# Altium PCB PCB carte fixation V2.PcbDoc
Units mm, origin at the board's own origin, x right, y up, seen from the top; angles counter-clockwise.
Board outline 50 x 70 mm, 2 copper layers (Top Layer, Bottom Layer); 0 components, 2 nets, 44 pads, 0 vias.
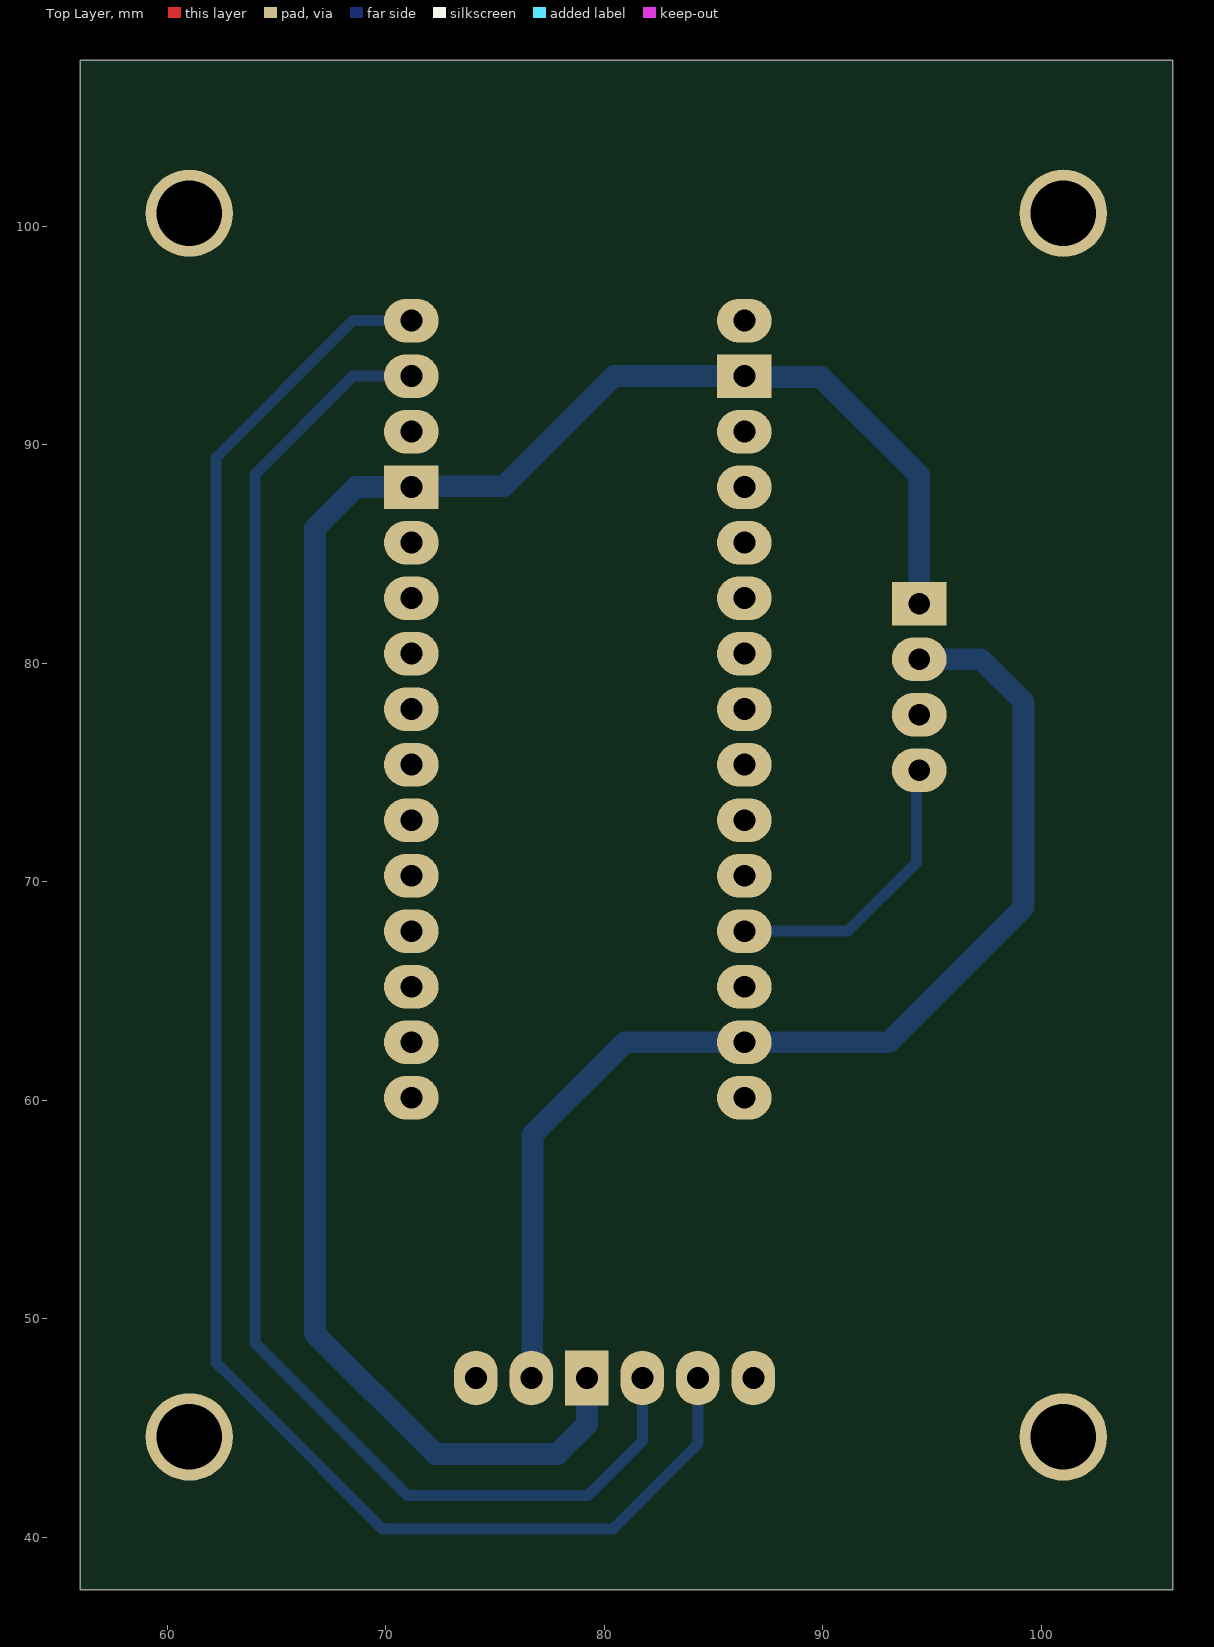
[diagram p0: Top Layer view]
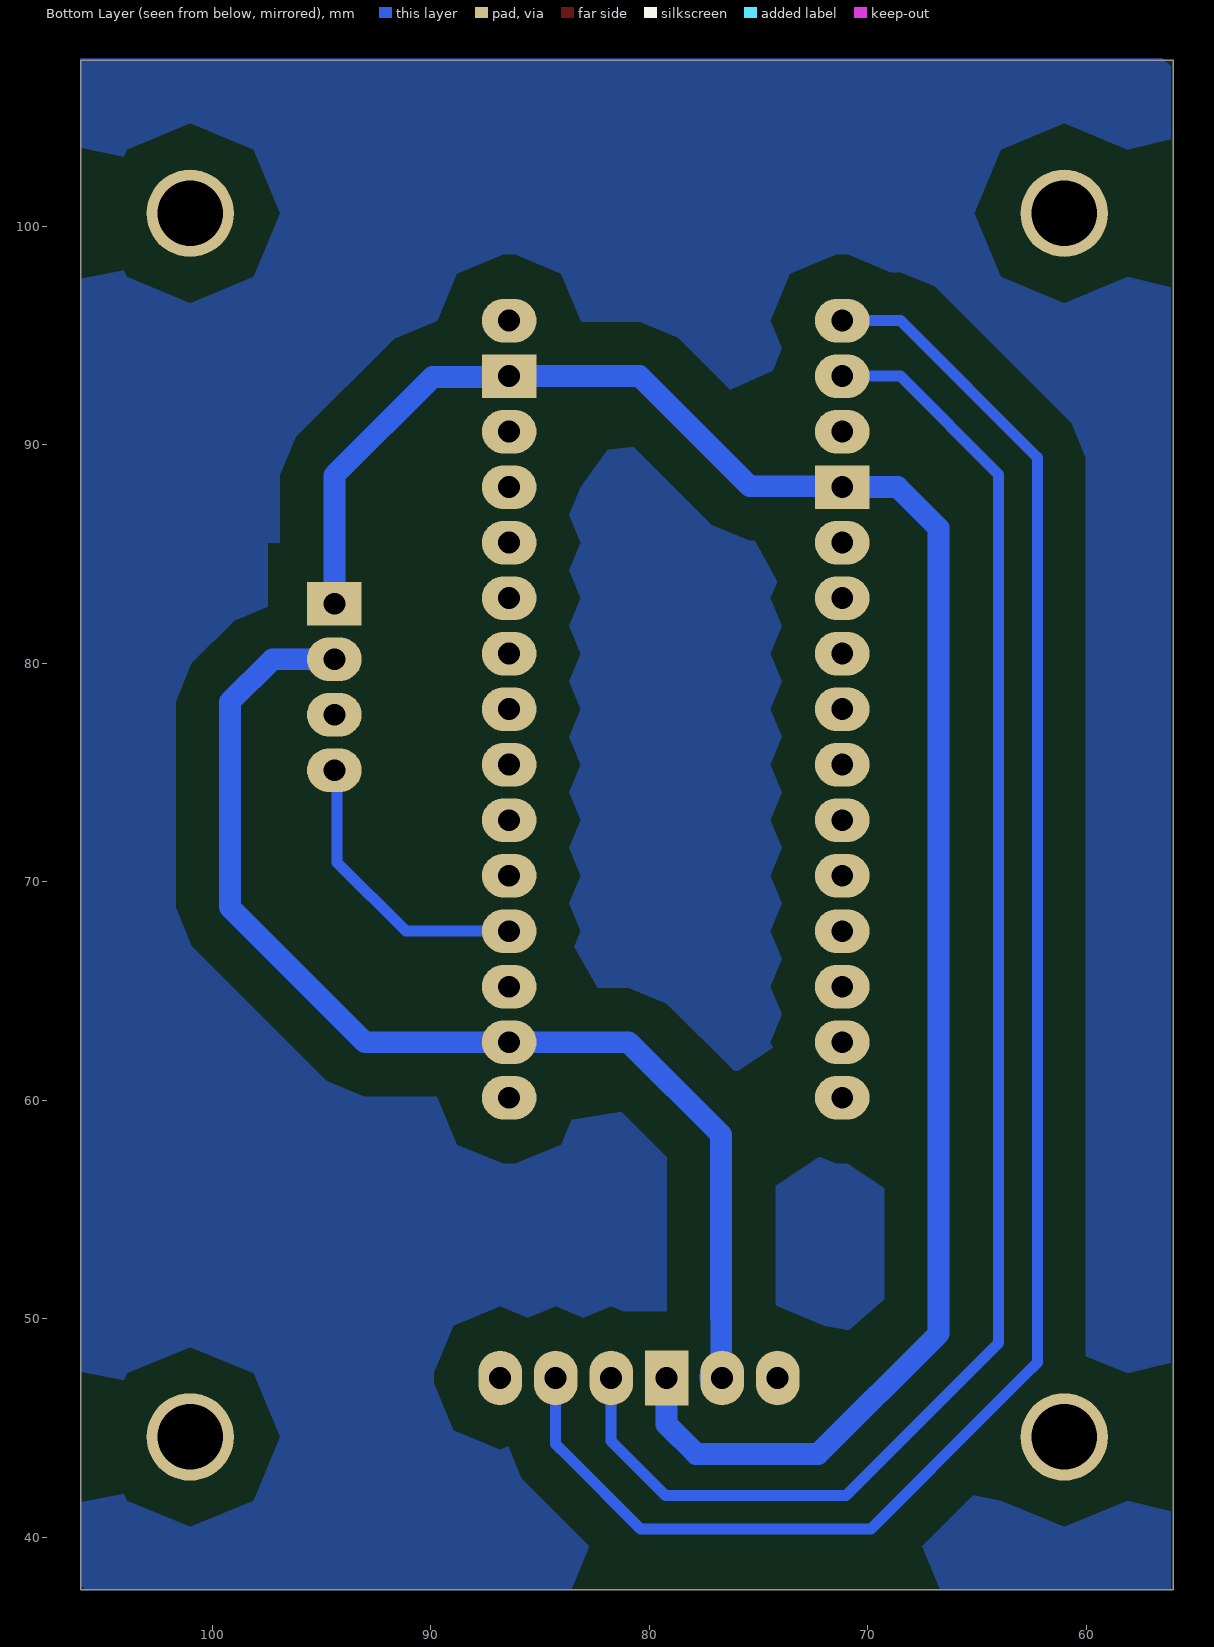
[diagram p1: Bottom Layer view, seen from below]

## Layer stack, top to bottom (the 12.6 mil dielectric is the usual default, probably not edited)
Top Solder: solder mask 0.0102, Solder Resist, Dk 3.5
Top Layer: signal copper 0.0356
Dielectric 1: dielectric 0.32, FR-4, Dk 4.8
Bottom Layer: signal copper 0.0356
Bottom Solder: solder mask 0.0102, Solder Resist, Dk 3.5

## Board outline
56.007,37.592 56.007,107.592 106.007,107.592 106.007,37.592

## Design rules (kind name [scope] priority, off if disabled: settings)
Clearance Keepout [ISPAD vs iskeepout or IsPad] p1: gap=0.05
Clearance Clearance_Plan [InPolygon] p2: gap=1.8
Clearance [All] p3: gap=0.5
PolygonConnect [All] p1: connectstyle=Relief reliefconductorwidth=0.254 reliefentries=4 polygonreliefangle="90 Angle" airgapwidth=0.254
RoutingVias [All] p1: holewidth=0.8 width=1.7 viastyle="Through Hole" minholewidth=0.8 minwidth=1.7 maxholewidth=0.8 maxwidth=1.7
SolderMaskExpansion [All] p1: expansion=0.102
Width LargeurePistesPuissance [InNet('ALIM') OR InNet('MASSE')] p1: maxlimit=2 minlimit=1 preferedwidth=2 minimp=50.000000 maximp=50.000000 favimp=50.000000
Width LargeurPistes [All] p2: maxlimit=1 minlimit=0.5 preferedwidth=0.8 minimp=50.000000 maximp=50.000000 favimp=50.000000
30 further rules are at their usual default settings.

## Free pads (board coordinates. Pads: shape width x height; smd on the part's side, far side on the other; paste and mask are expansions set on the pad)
  round 4 hole 3: 12(61.007,44.592) 12(61.007,100.592) 12(101.007,44.592) 12(101.007,100.592)
  oval 2.5x2 hole 1: 13(71.168,60.119) 13(71.168,62.659) 13(71.168,65.199) 13(71.168,67.739) 13(71.168,70.279) 13(71.168,72.819) 13(71.168,75.359) 13(71.168,77.899) 13(71.168,80.439) 13(71.168,82.979) 13(71.168,85.519) 13(71.168,90.599) 13(71.168,93.139) 13(71.168,95.679) 13(86.408,60.119) 13(86.408,62.659) 13(86.408,65.199) 13(86.408,67.739) 13(86.408,70.279) 13(86.408,72.819) 13(86.408,75.359) 13(86.408,77.899) 13(86.408,80.439) 13(86.408,82.979) 13(86.408,85.519) 13(86.408,88.059) 13(86.408,90.599) 13(86.408,95.679) 13(94.409,75.105) 13(94.409,77.645) 13(94.409,80.185)
  rect 2.5x2 hole 1: 13(71.168,88.059) 13(86.408,93.139) 13(94.409,82.725)
  oval 2x2.5 hole 1: 13(74.12,47.292) 13(76.66,47.292) 13(81.74,47.292) 13(84.28,47.292) 13(86.82,47.292)
  rect 2x2.5 hole 1: 13(79.2,47.292)

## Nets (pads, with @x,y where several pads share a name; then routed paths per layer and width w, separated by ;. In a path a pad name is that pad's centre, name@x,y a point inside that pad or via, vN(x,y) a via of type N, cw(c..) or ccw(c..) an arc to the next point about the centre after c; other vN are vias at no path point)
ALIM: pad.13@76.66,47.292 pad.13@86.408,62.659 pad.13@94.409,80.185 | length 52.9
  Bottom Layer w1: pad.13@76.7,47.332 76.7,50.082 76.708,50.09 76.708,58.42 80.947,62.659 86.408,62.659 93.012,62.659 99.187,68.834 99.187,78.232 97.234,80.185 pad.13@94.409,80.185
  Bottom Layer w2: pad.13@76.66,47.292 pad.13@76.7,47.332
MASSE: pad.13@71.168,88.059 pad.13@79.2,47.292 pad.13@86.408,93.139 pad.13@94.409,82.725 | length 91.2
  Bottom Layer w1: pad.13@71.168,88.059 68.628,88.059 66.754,86.185 66.754,49.324 72.263,43.815 77.851,43.815 79.2,45.164 pad.13@79.2,47.292 ; pad.13@71.208,88.099 75.399,88.099 80.439,93.139 pad.13@86.408,93.139 ; 87.694,93.099 89.908,93.099 94.409,88.598 pad.13@94.409,82.725
copper on no net: | length 170.2
  Top Layer w0.254: 81.806,46.373 81.806,47.244 ; 84.606,47.244 84.606,47.947
  Bottom Layer w0.5: 71.168,93.139 68.501,93.139 64.008,88.646 64.008,48.895 70.993,41.91 79.248,41.91 81.74,44.402 81.74,46.599 ; 71.168,95.679 68.501,95.679 62.23,89.408 62.23,79.502 62.23,48.006 62.865,47.371 64.262,45.974 69.85,40.386 80.391,40.386 83.693,43.688 84.28,44.275 84.28,47.292 ; 86.408,67.739 91.137,67.739 94.282,70.884 94.282,74.978

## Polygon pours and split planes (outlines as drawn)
no net on Bottom Layer "botton" (solid, pour order 0): 56.261,107.442 56.515,107.696 106.045,107.696 106.045,37.846 105.918,37.719 105.791,37.592 56.134,37.592 56.134,107.315 56.261,107.442

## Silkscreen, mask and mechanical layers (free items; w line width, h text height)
Mechanical 1:
  the board outline again, w0.254
Mechanical 3:
  text "STM32L4" at 71.168,98.823 h1.52
  text "D1" at 73.406,95.377 h1.02
  text "VIN" at 82.931,95.25 h1.02
  text "D0" at 73.406,92.837 h1.02
  text "GND" at 82.931,92.837 h1.02
  text "RST" at 82.931,90.424 h1.02
  text "RST" at 73.406,90.17 h1.02
  text "5V" at 82.931,87.63 h1.02
  text "GND" at 73.279,86.995 h1.02
  text "A7" at 82.931,85.344 h1.02
  text "D2" at 73.406,85.217 h1.02
  text "D3" at 73.406,82.55 h1.02
  text "A6" at 82.931,82.55 h1.02
  text "GND" at 91.186,82.296 h0.5
  text "D4" at 73.406,80.264 h1.02
  text "A5" at 82.931,80.01 h1.02
  text "VCC" at 91.186,79.756 h0.5
  text "D5" at 73.406,77.851 h1.02
  text "A4" at 82.931,77.724 h1.02
  text "NC" at 91.186,77.216 h0.5
  text "A3" at 82.931,75.311 h1.02
  text "D6" at 73.406,75.184 h1.02
  text "SIG" at 91.186,74.676 h0.5
  text "D7" at 73.406,72.644 h1.02
  text "A2" at 82.931,72.644 h1.02
  text "A1" at 82.931,70.231 h1.02
  text "D8" at 73.406,69.977 h1.02
  text "A0" at 82.931,67.437 h1.02
  text "D9" at 73.406,67.31 h1.02
  text "REF" at 82.931,64.897 h1.02
  text "D10" at 73.406,64.77 h1.02
  text "D11" at 73.406,62.484 h1.02
  text "3V3" at 82.931,62.484 h1.02
  text "D13" at 82.931,59.944 h1.02
  text "D12" at 73.406,59.69 h1.02
  text "EN" at 73.533,48.895 h0.5
  text "GND" at 78.486,48.895 h0.5
  text "3V3" at 75.946,44.831 h0.5
  text "RST" at 86.36,44.45 h0.5
  text "TX" at 81.661,44.323 h0.5
  text "RX" at 83.947,44.323 h0.5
